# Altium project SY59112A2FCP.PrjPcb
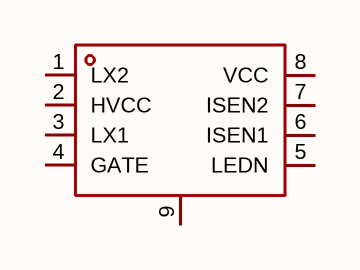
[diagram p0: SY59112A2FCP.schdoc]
1 sheet, 1 parts. Net scope: global (net labels, ports and power ports of the same name join across sheets).

## Sheet SY59112A2FCP.schdoc
size 127 x 101 mm

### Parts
U?  sy59112a2fcp  [ESOP-8_L4.9-W3.9-P1.27-LS6.0-BL-EP-1]  (value not drawn)

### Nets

Not connected (* = marked no-connect by the designer): U? 1(LX2) 2(HVCC) 3(LX1) 4(GATE) 5(LEDN) 6(ISEN1) 7(ISEN2) 8(VCC) 9(GND)

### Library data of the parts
U? = sy59112a2fcp: 类型:-;工作电压(DC):-;开关频率:-;通道数:1;输出电压:-;输出电流:-;调光:TRIAC;拓扑结构:-;; Manufacturer: Silergy(矽力杰); AddInBom: yes; ModelId: 1edf17d9e1eb44b9aabe355eb95382d1; ModelTransform: 192.913,236.22,0,0,0,0,0,0,0; Number of Channels: 1; Dimming: TRIAC; Switch Tube (Built-In/External): 内置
